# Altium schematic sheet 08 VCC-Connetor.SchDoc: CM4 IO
size 420 x 297 mm; Page Create Date: March  8, 1995; Page Number: 8; Page Size: A3; Comment: radxa_1010; Page Count: 19; RevCode: V1.10; Doc: 08 VCC-Connetor; DsnPath: D:\WMS\黄工\[RC126]CM4_IO_V1.10\[RC126]_V1.10\CM4 IO_V1.10.DSN; SchematicName: CM4 IO V1.10; PageName: 08 VCC-Connetor; PageSize: A3; TopSchematic: True
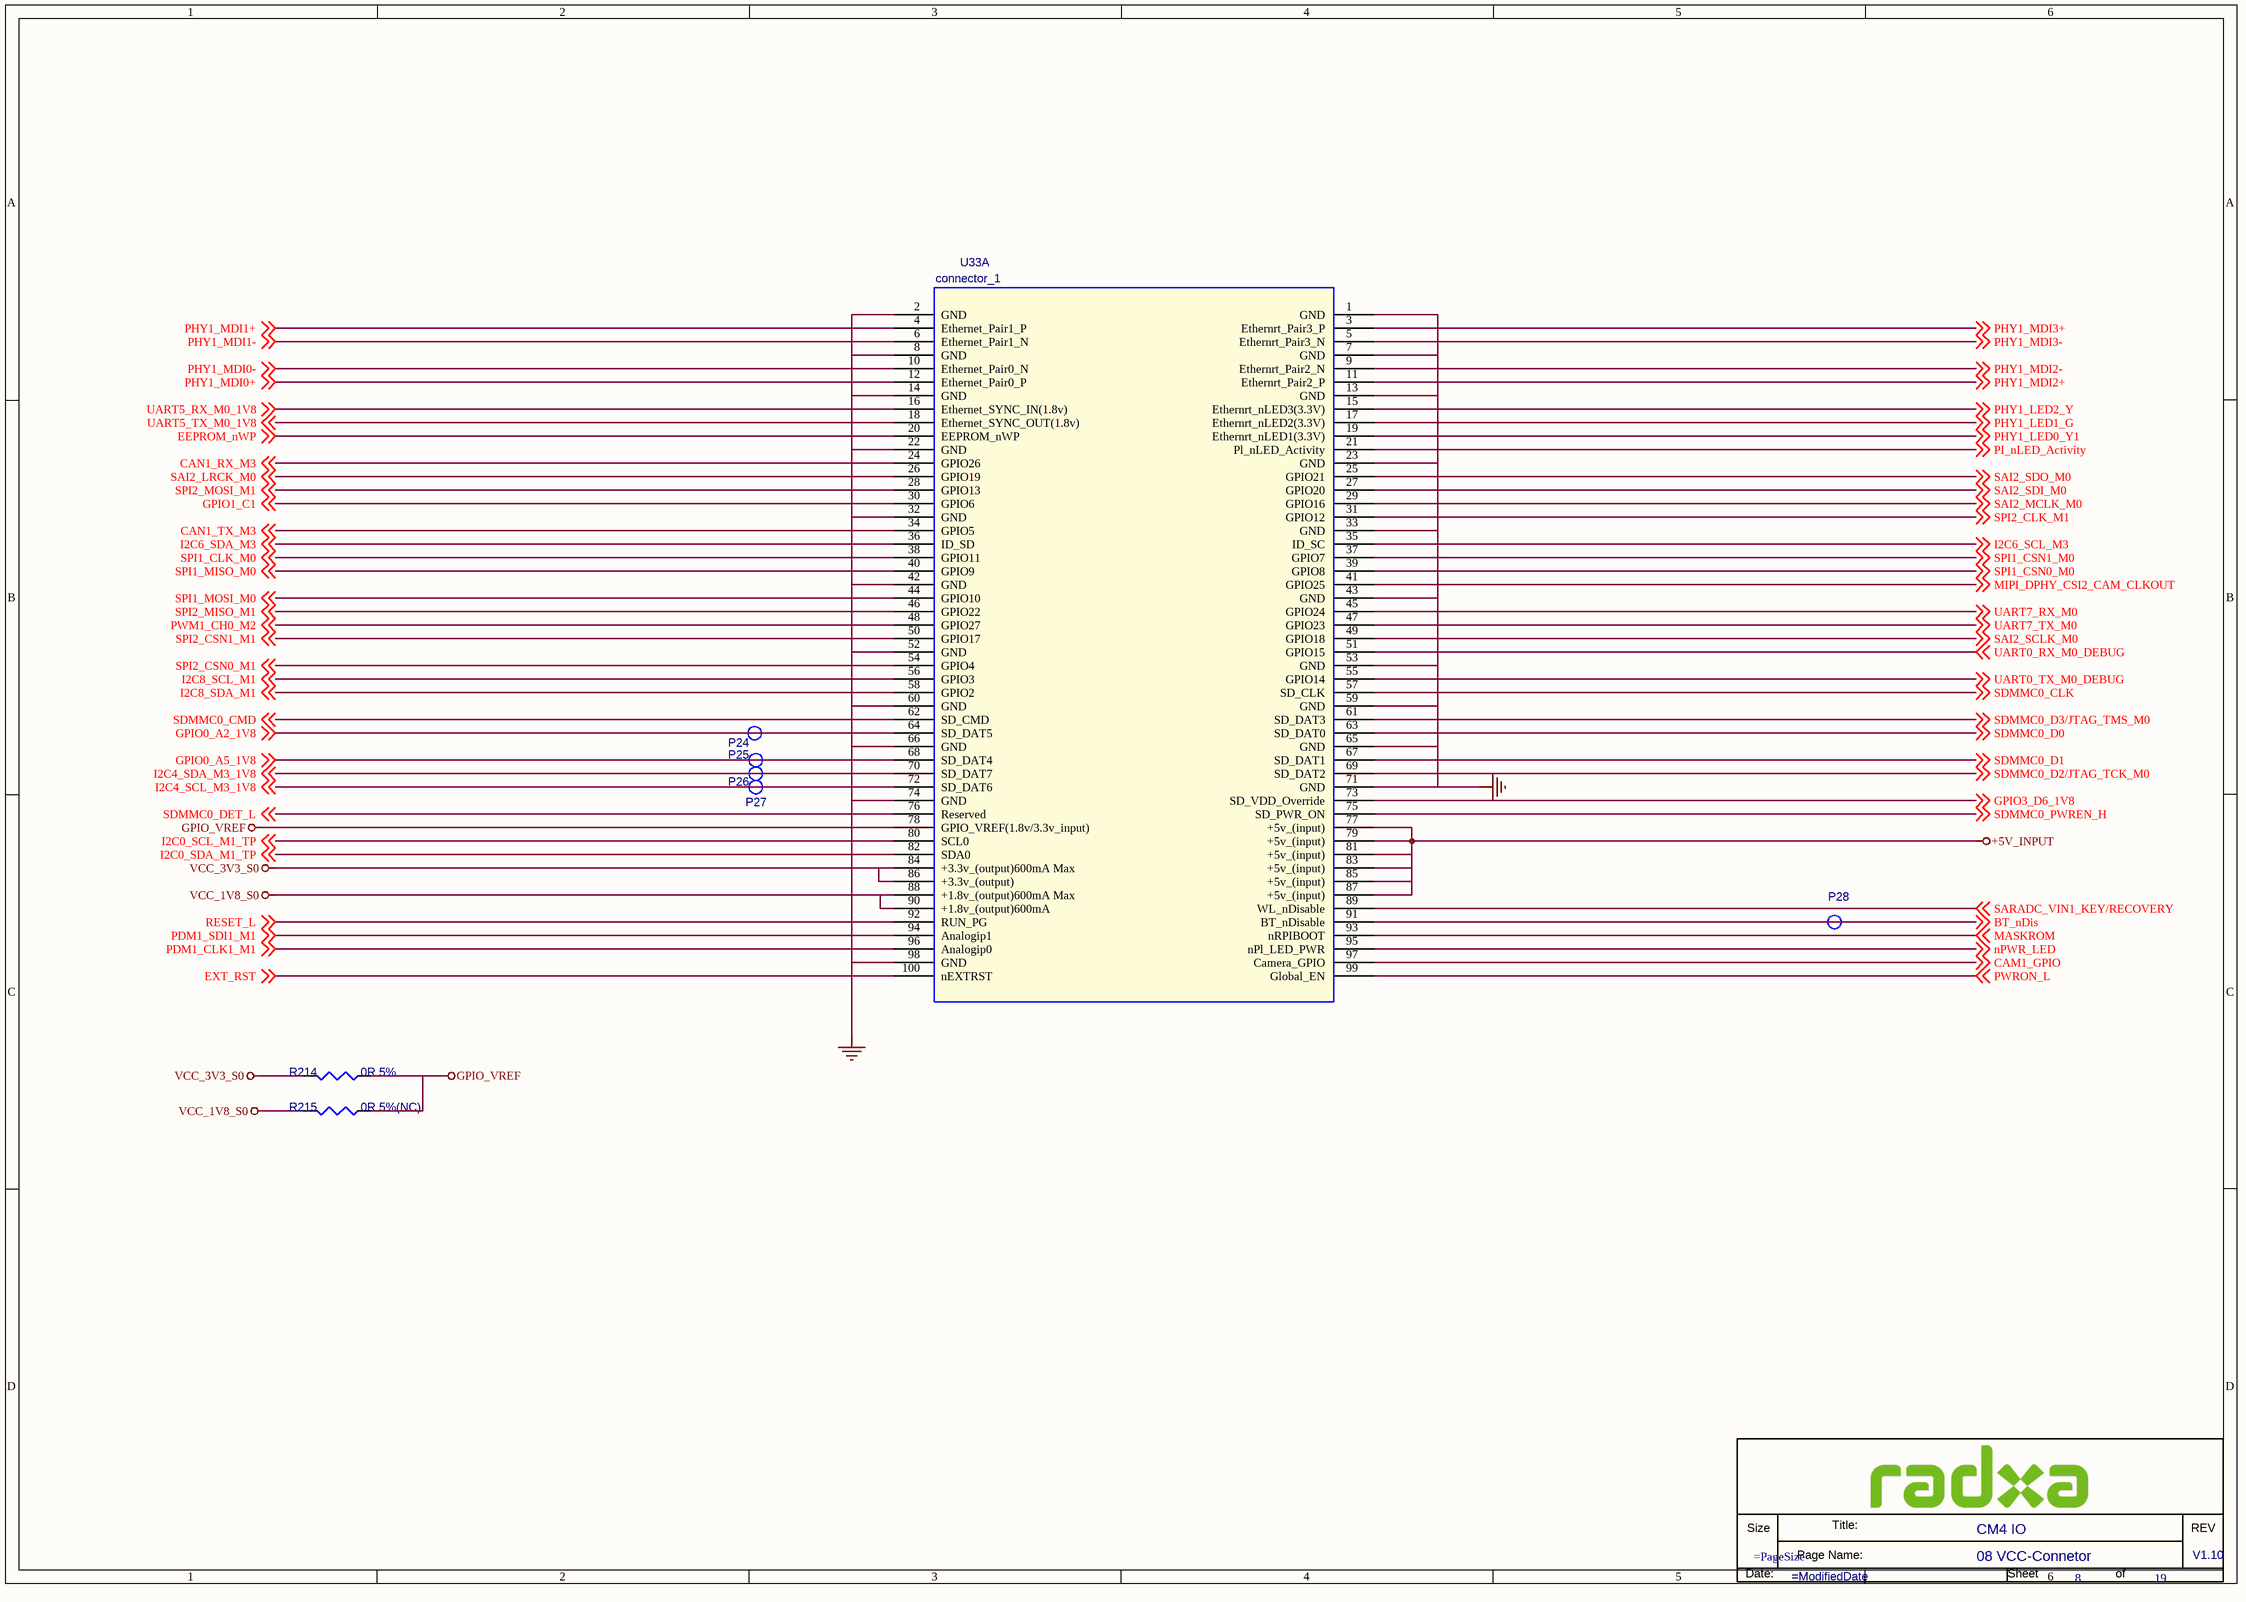
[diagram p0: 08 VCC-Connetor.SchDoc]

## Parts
*  Doc: 08 VCC-Connetor  RevCode: V1.10  Title: CM4 IO  Page Number: 8  Page Count: 19  (hidden comment: radxa_1010)  (graphical)
P24  TEST  [TEST]  (value not drawn)
P25  TEST  [TEST]  (value not drawn)
P26  TEST  [TEST]  (value not drawn)
P27  TEST  [TEST]  (value not drawn)
P28  TEST  [TEST]  (value not drawn)
R214  0R 5%  [R0402]
R215  0R 5%(NC)  [R0402]
U33  connector_1  [BTB_SMD100X2_0D4_STA]  (part A of 2)

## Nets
+5V_INPUT: U33.77(+5v_(input)) U33.79(+5v_(input)) U33.81(+5v_(input)) U33.83(+5v_(input)) U33.85(+5v_(input)) U33.87(+5v_(input))
GND: U33.1(GND) U33.2(GND) U33.7(GND) U33.8(GND) U33.13(GND) U33.14(GND) U33.22(GND) U33.23(GND) U33.32(GND) U33.33(GND) U33.42(GND) U33.43(GND) U33.52(GND) U33.53(GND) U33.59(GND) U33.60(GND) U33.65(GND) U33.66(GND) U33.71(GND) U33.74(GND) U33.98(GND)
GPIO_VREF: R214.1 R215.1 U33.78(GPIO_VREF(1.8v/3.3v_input))
VCC_1V8_S0: R215.2 U33.88(+1.8v_(output)600mA_Max) U33.90(+1.8v_(output)600mA)
VCC_3V3_S0: R214.2 U33.84(+3.3v_(output)600mA_Max) U33.86(+3.3v_(output))
BT_nDis: P28.1 U33.91(BT_nDisable) ; off-sheet BT_nDis
CAM1_GPIO: U33.97(Camera_GPIO) ; off-sheet CAM1_GPIO
CAN1_RX_M3: U33.24(GPIO26) ; off-sheet CAN1_RX_M3
CAN1_TX_M3: U33.34(GPIO5) ; off-sheet CAN1_TX_M3
EEPROM_nWP: U33.20(EEPROM_nWP) ; off-sheet EEPROM_nWP
EXT_RST: U33.100(nEXTRST) ; off-sheet EXT_RST
GPIO0_A2_1V8: P24.1 U33.64(SD_DAT5) ; off-sheet GPIO0_A2_1V8
GPIO0_A5_1V8: P25.1 U33.68(SD_DAT4) ; off-sheet GPIO0_A5_1V8
GPIO1_C1: U33.30(GPIO6) ; off-sheet GPIO1_C1
GPIO3_D6_1V8: U33.73(SD_VDD_Override) ; off-sheet GPIO3_D6_1V8
I2C0_SCL_M1_TP: U33.80(SCL0) ; off-sheet I2C0_SCL_M1_TP
I2C0_SDA_M1_TP: U33.82(SDA0) ; off-sheet I2C0_SDA_M1_TP
I2C4_SCL_M3_1V8: P27.1 U33.72(SD_DAT6) ; off-sheet I2C4_SCL_M3_1V8
I2C4_SDA_M3_1V8: P26.1 U33.70(SD_DAT7) ; off-sheet I2C4_SDA_M3_1V8
I2C6_SCL_M3: U33.35(ID_SC) ; off-sheet I2C6_SCL_M3
I2C6_SDA_M3: U33.36(ID_SD) ; off-sheet I2C6_SDA_M3
I2C8_SCL_M1: U33.56(GPIO3) ; off-sheet I2C8_SCL_M1
I2C8_SDA_M1: U33.58(GPIO2) ; off-sheet I2C8_SDA_M1
MASKROM: U33.93(nRPIBOOT) ; off-sheet MASKROM
MIPI_DPHY_CSI2_CAM_CLKOUT: U33.41(GPIO25) ; off-sheet MIPI_DPHY_CSI2_CAM_CLKOUT
nPWR_LED: U33.95(nPl_LED_PWR) ; off-sheet nPWR_LED
PDM1_CLK1_M1: U33.96(Analogip0) ; off-sheet PDM1_CLK1_M1
PDM1_SDI1_M1: U33.94(Analogip1) ; off-sheet PDM1_SDI1_M1
PHY1_LED0_Y1: U33.19(Ethernrt_nLED1(3.3V)) ; off-sheet PHY1_LED0_Y1
PHY1_LED1_G: U33.17(Ethernrt_nLED2(3.3V)) ; off-sheet PHY1_LED1_G
PHY1_LED2_Y: U33.15(Ethernrt_nLED3(3.3V)) ; off-sheet PHY1_LED2_Y
PHY1_MDI0+: U33.12(Ethernet_Pair0_P) ; off-sheet PHY1_MDI0+
PHY1_MDI0-: U33.10(Ethernet_Pair0_N) ; off-sheet PHY1_MDI0-
PHY1_MDI1+: U33.4(Ethernet_Pair1_P) ; off-sheet PHY1_MDI1+
PHY1_MDI1-: U33.6(Ethernet_Pair1_N) ; off-sheet PHY1_MDI1-
PHY1_MDI2+: U33.11(Ethernrt_Pair2_P) ; off-sheet PHY1_MDI2+
PHY1_MDI2-: U33.9(Ethernrt_Pair2_N) ; off-sheet PHY1_MDI2-
PHY1_MDI3+: U33.3(Ethernrt_Pair3_P) ; off-sheet PHY1_MDI3+
PHY1_MDI3-: U33.5(Ethernrt_Pair3_N) ; off-sheet PHY1_MDI3-
PI_nLED_Activity: U33.21(Pl_nLED_Activity) ; off-sheet PI_nLED_Activity
PWM1_CH0_M2: U33.48(GPIO27) ; off-sheet PWM1_CH0_M2
PWRON_L: U33.99(Global_EN) ; off-sheet PWRON_L
RESET_L: U33.92(RUN_PG) ; off-sheet RESET_L
SAI2_LRCK_M0: U33.26(GPIO19) ; off-sheet SAI2_LRCK_M0
SAI2_MCLK_M0: U33.29(GPIO16) ; off-sheet SAI2_MCLK_M0
SAI2_SCLK_M0: U33.49(GPIO18) ; off-sheet SAI2_SCLK_M0
SAI2_SDI_M0: U33.27(GPIO20) ; off-sheet SAI2_SDI_M0
SAI2_SDO_M0: U33.25(GPIO21) ; off-sheet SAI2_SDO_M0
SARADC_VIN1_KEY/RECOVERY: U33.89(WL_nDisable) ; off-sheet SARADC_VIN1_KEY/RECOVERY
SDMMC0_CLK: U33.57(SD_CLK) ; off-sheet SDMMC0_CLK
SDMMC0_CMD: U33.62(SD_CMD) ; off-sheet SDMMC0_CMD
SDMMC0_D0: U33.63(SD_DAT0) ; off-sheet SDMMC0_D0
SDMMC0_D1: U33.67(SD_DAT1) ; off-sheet SDMMC0_D1
SDMMC0_D2/JTAG_TCK_M0: U33.69(SD_DAT2) ; off-sheet SDMMC0_D2/JTAG_TCK_M0
SDMMC0_D3/JTAG_TMS_M0: U33.61(SD_DAT3) ; off-sheet SDMMC0_D3/JTAG_TMS_M0
SDMMC0_DET_L: U33.76(Reserved) ; off-sheet SDMMC0_DET_L
SDMMC0_PWREN_H: U33.75(SD_PWR_ON) ; off-sheet SDMMC0_PWREN_H
SPI1_CLK_M0: U33.38(GPIO11) ; off-sheet SPI1_CLK_M0
SPI1_CSN0_M0: U33.39(GPIO8) ; off-sheet SPI1_CSN0_M0
SPI1_CSN1_M0: U33.37(GPIO7) ; off-sheet SPI1_CSN1_M0
SPI1_MISO_M0: U33.40(GPIO9) ; off-sheet SPI1_MISO_M0
SPI1_MOSI_M0: U33.44(GPIO10) ; off-sheet SPI1_MOSI_M0
SPI2_CLK_M1: U33.31(GPIO12) ; off-sheet SPI2_CLK_M1
SPI2_CSN0_M1: U33.54(GPIO4) ; off-sheet SPI2_CSN0_M1
SPI2_CSN1_M1: U33.50(GPIO17) ; off-sheet SPI2_CSN1_M1
SPI2_MISO_M1: U33.46(GPIO22) ; off-sheet SPI2_MISO_M1
SPI2_MOSI_M1: U33.28(GPIO13) ; off-sheet SPI2_MOSI_M1
UART0_RX_M0_DEBUG: U33.51(GPIO15) ; off-sheet UART0_RX_M0_DEBUG
UART0_TX_M0_DEBUG: U33.55(GPIO14) ; off-sheet UART0_TX_M0_DEBUG
UART5_RX_M0_1V8: U33.16(Ethernet_SYNC_IN(1.8v)) ; off-sheet UART5_RX_M0_1V8
UART5_TX_M0_1V8: U33.18(Ethernet_SYNC_OUT(1.8v)) ; off-sheet UART5_TX_M0_1V8
UART7_RX_M0: U33.45(GPIO24) ; off-sheet UART7_RX_M0
UART7_TX_M0: U33.47(GPIO23) ; off-sheet UART7_TX_M0

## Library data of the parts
P24 = TESTPOINT1: Part Reference: P24; PCB Footprint: TP_0R70
P25 = TESTPOINT1: Part Reference: P25; PCB Footprint: TP_0R70
P26 = TESTPOINT1: Part Reference: P26; PCB Footprint: TP_0R70
P27 = TESTPOINT1: Part Reference: P27; PCB Footprint: TP_0R70
P28 = TESTPOINT1: Part Reference: P28; PCB Footprint: TP_0R70
R214 = R: SMD  0201  0R  1/20W  ±5%  ROHS; Part Reference: R214; Part Number: A1R01.00027; PCB Footprint: R0201; Preferred: 6715f349cd0bc5; Temp Coeff: -55℃ to +125℃
R215 = R: SMD  0201  0R  1/20W  ±5%  ROHS; Part Reference: R215; Part Number: A1R01.00027; PCB Footprint: R0201; Temp Coeff: -55℃ to +125℃; Preferred: 6715f349cd0bc5
U33 = HETER_4: Part Reference: U33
